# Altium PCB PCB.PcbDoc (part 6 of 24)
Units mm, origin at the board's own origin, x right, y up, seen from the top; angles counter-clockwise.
Board outline 100 x 160 mm, 10 copper layers (TOP_L1, L2, L3, L4, L5, L6, L7, L8, L9, BOTTOM_L10), stack 1.946 mm thick; 1358 components, 1149 nets, 6777 pads, 10914 vias.
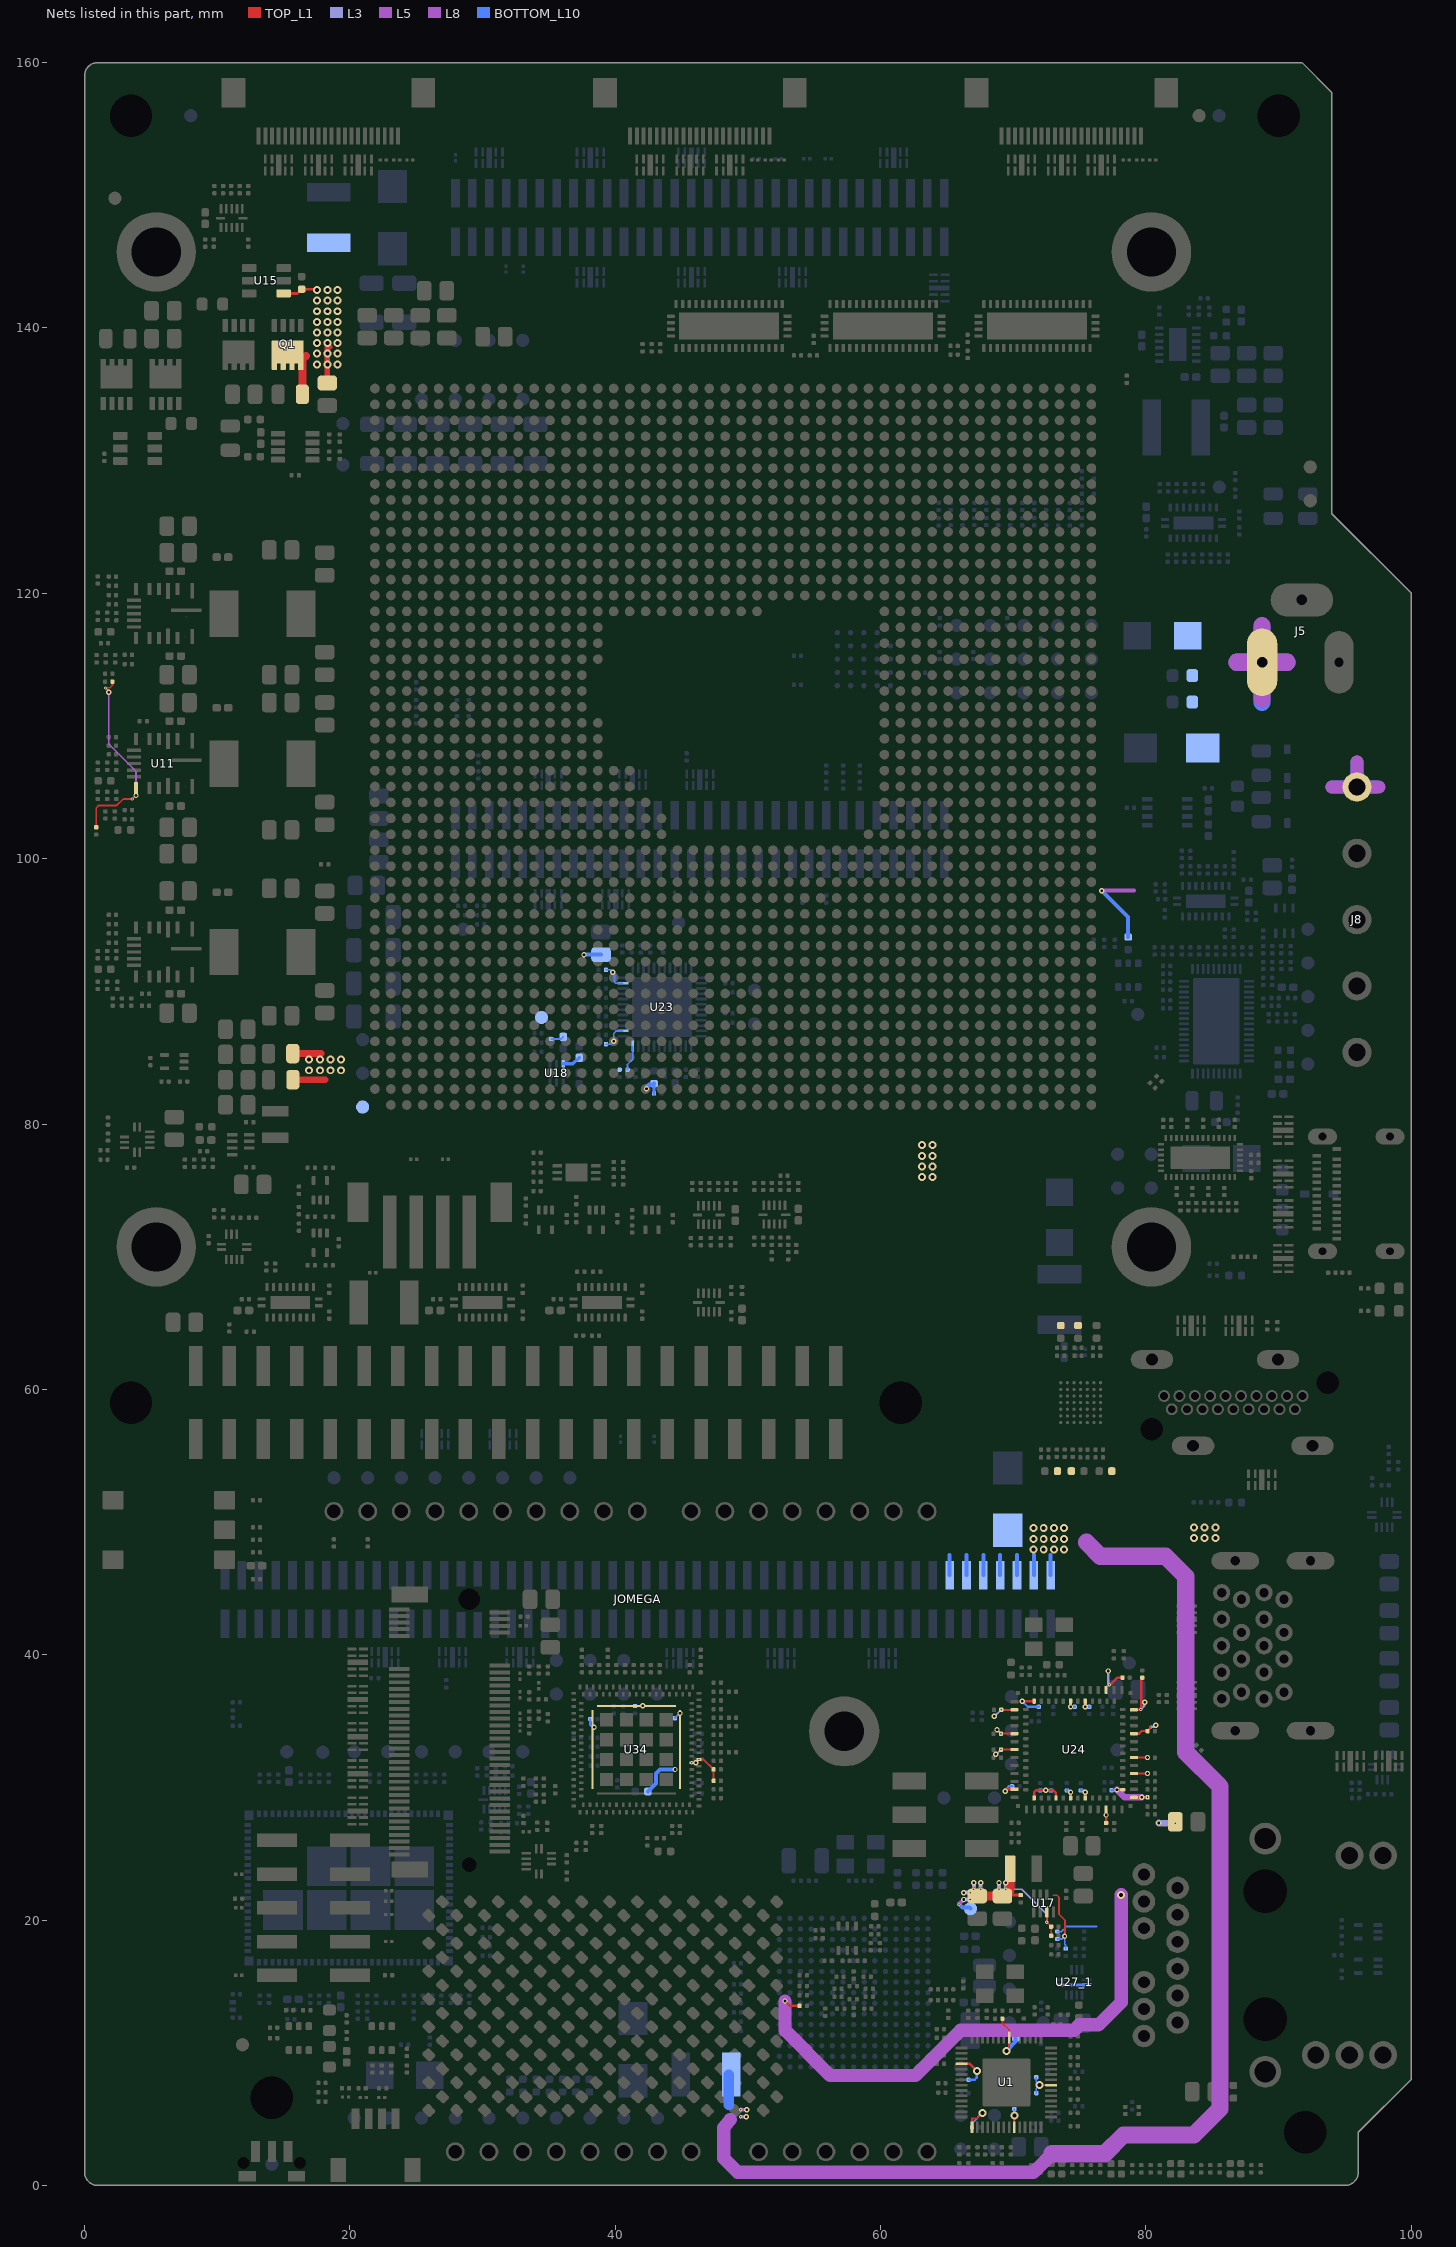
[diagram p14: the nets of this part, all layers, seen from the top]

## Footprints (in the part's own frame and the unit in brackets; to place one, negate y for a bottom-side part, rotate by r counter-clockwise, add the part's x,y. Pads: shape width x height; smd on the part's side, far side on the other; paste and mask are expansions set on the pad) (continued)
"WSON8 TI DDR 3x3mm 12 pins pitch 0.5mm" [mm]
  rrect25% 0.62x0.25 smd mask+0.05: 1(-1.39,1.25) 2(-1.39,0.75) 3(-1.39,0.25) 4(-1.39,-0.25) 5(-1.39,-0.75) 6(-1.39,-1.25) 7(1.39,-1.25) 8(1.39,-0.75) 9(1.39,-0.25) 10(1.39,0.25) 11(1.39,0.75) 12(1.39,1.25)
  rect 1.3x2.5 smd paste-2539.97 mask+0.05: 13(0,0)
  silkscreen extent -1.7,1.73 -1.6,1.83, body extent -1.51,-1.5 1.51,1.5, height 0.8

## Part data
C1 C2 C3 C4 C5 C6 C7 C8 C10 C11 C12 C13 C14 C16 C17 C18 C19 C20 C21 C22 C25 C26 C27 C28 C29 C30 C31 C32 C33 C34 C36 C43 C45 C46 C47 C49 C54 C55 C56 C57 C58 C59 C60 C61 C62 C67 C68 C69_1 C69_2 C69_3 C71 C94 C101 C111 C112 C113 C118 C119 C123 C124 C128 C129 C130 C131 C134 C146 C150 C152 C154 C156 C158 C163 C165 C166 C168 C170 C172_1 C172_2 C172_3 C172_4 C172_5 C173_1 C173_2 C173_3 C173_4 C173_5 C174_1 C174_2 C174_3 C174_4 C174_5 C175_1 C175_2 C175_3 C175_4 C175_5 C179_1 C179_2 C179_3 C179_4 C179_5 C179_6 C180 C181 C182 C183 C184 C185 C186 C188 C189 C190 C191 C192 C193 C194 C195 C196 C197 C198 C199 C202 C203 C204 C206 C207 C210 C211 C212 C213 C214 C215 C224 C225 C228 C229 C230 C231 C232 C233 C234 C235 C236 C237 C238 C239 C240 C241 C242 C243 C244 C245 C247 C251 C257 C258 C260 C262 C263 C265 C266 C267 C268 C269 C270 C271 C272 C273 C274 C275 C277 C278 C279 C281 C282 C283 C289 C291 C297 C300 C305 C306 C309 C310 C314 C324 C325 C328 C329 C330 C331 C338: library part C0113-A.6, "CAP CHIP 0201 100nF 10% 10V X5R", Case Code (Imperial)=0201, Dielectric=X5R, Manufacturer="Samsung Electro-Mechanics", Tolerance=10%, Voltage=10V
C9 C15 C42 C48 C63 C65 C85 C95 C106 C107 C108 C109 C110 C114 C136 C151 C153 C155 C157 C159 C160 C161 C162 C164 C167 C169 C205 C209 C217 C253 C254 C304 C308 C345 C346 C347 C348 C360: library part C0002-A.15, "CAP CHIP 0201 1uF 20% 6.3V X5R", Case Code (Imperial)=0201, Dielectric=X5R, Manufacturer=Murata, Tolerance=20%, Voltage=6.3V
C23 C24 C97 C105 C218 C219: library part C0003-A.15, "CAP CHIP 0201 12pF 5% 25V C0G", Case Code (Imperial)=0201, Dielectric=C0G, Manufacturer=Murata, Tolerance=5%, Voltage=25V
C35 C37 C38 C39 C81 C82 C83 C103 C104 C115 C120 C125 C147 C171 C177 C178 C187 C201 C221 C222 C223 C226 C227 C249 C250 C252 C255 C276 C311 C312 C313 C315 C316 C317 C318 C355 C359: library part C0199-A.1, "CAP CHIP 0805 47uF 20% 6.3V X5R", Case Code (Imperial)=0805, Dielectric=X5R, Manufacturer=KEMET, Tolerance=20%, Voltage=6.3V
C40 C41: library part C0197-A.2, "CAP CHIP 0402 390pF 10% 50V X7R", Case Code (Imperial)=0402, Dielectric=X7R, Manufacturer=Murata, Tolerance=10%, Voltage=50V
C44 C64 C70 C72 C132 C133 C137 C139 C176_1 C176_2 C176_3 C176_4 C176_5 C220_1 C220_2 C220_3 C220_4 C220_5 C259 C286 C287 C296 C332: library part C0037-A.14, "CAP CHIP 0402 4.7uF 20% 6V3 X5R", Case Code (Imperial)=0402, Dielectric=X5R, Manufacturer=Hottech, Manufacturer 2="Samsung Electro-Mechanics", Manufacturer 3="Murata Electronics", Part number 2=CL05A475KQ5NRNC, Part number 3=GRM155R60J475ME47D, Tolerance=20%, Voltage=6.3V
C50 C51 C52 C53: library part C0201-A.1, "CAP CHIP 0201 330nF 10% 25V X5R", Case Code (Imperial)=0201, Dielectric=X5R, Manufacturer="Samsung Electro-Mechanics", Tolerance=10%, Voltage=25V
C66: library part C0059-A.14, "CAP CHIP 0805 4.7nF 10% 1000V X7R", Case Code (Imperial)=0805, Dielectric=X7R, Manufacturer="PSA Shenzen", Manufacturer 2=KEMET, Part number 2=C0805V472KDRACTU, Part number 3=C0805C472KDRACTU, Tolerance=10%, Voltage=1kV
C73 C74 C76 C77 C78 C87 C88 C89 C98 C99 C117 C122 C135 C200 C208 C216 C288 C292 C294 C302 C352 C356 C357: library part C0158-A.3, "CAP CHIP 0805 10uF 20% 50V X5R", Case Code (Imperial)=0805, Dielectric=X5R, Manufacturer="Murata Electronics", Tolerance=20%, Voltage=50V
C75 C79 C84 C86 C90 C96 C100 C301 C303 C319 C320 C321 C333 C350 C351 C353 C354: library part C0015-A.14, "CAP CHIP 0402 100nF 10% 50V X5R", Case Code (Imperial)=0402, Dielectric=X5R, Manufacturer=Murata, Tolerance=10%, Voltage=50V
C80 C91 C102 C121 C126: library part C0114-A.6, "CAP CHIP 0201 33pF 5% 6.3V C0G", Case Code (Imperial)=0201, Dielectric=C0G, Manufacturer="Murata Electronics", Tolerance=5%, Voltage=6.3V
C92 C93 C140 C141 C142 C143 C148 C149 C334 C335 C336 C337: library part C0166-A.1, "CAP CHIP 1206 100uF 20% 10V X5R", Case Code (Imperial)=1206, Dielectric=X5R, Manufacturer=Murata, Tolerance=20%, Voltage=10V
C116 C127 C138: library part C0009-A.15, "CAP CHIP 0402 10nF 10% 50V X7R", Case Code (Imperial)=0402, Dielectric=X7R, Manufacturer=Hottech, Manufacturer 2="Murata Electronics", Manufacturer 3=YAGEO, Part number 2=CC0402KRX7R9BB103, Tolerance=10%, Voltage=50V
C144 C145: library part C0198-A.1, "CAP CHIP 0201 180pF 5% 50V C0G", Case Code (Imperial)=0201, Dielectric=C0G, Manufacturer=Murata, Tolerance=5%, Voltage=50V
C246_1 C246_2 C246_3 C246_4 C246_5 C246_6: library part C0112-A.6, "CAP CHIP 0201 10nF 10% 6.3V X7R", Case Code (Imperial)=0201, Dielectric=X7R, Manufacturer=Murata, Manufacturer 2=Yageo, Tolerance=10%, Voltage=6.3V
C248 C295: library part C0144-A.3, "CAP CHIP 0201 10pF 5% 50V C0G", Case Code (Imperial)=0201, Dielectric=C0G, Manufacturer=Yageo, Tolerance=5%, Voltage=50V
C256 C293: library part C0209-A.1, "CAP CHIP 0805 10nF 250V X7R", Case Code (Imperial)=0805, Dielectric=X7R, Manufacturer=Murata, Tolerance=10%, Voltage=250V
C261 C264: library part C0203-A.1, "CAP CHIP 0201 6pF 0.25pF 25V C0G", Case Code (Imperial)=0201, Dielectric=C0G, Manufacturer=Murata, Tolerance=0.25pF, Voltage=25V
C280 C284 C290 C298: library part C0113-A.6, "CAP CHIP 0201 100nF 10% 10V X5R", Case Code (Imperial)=0201, Dielectric=X5R, Manufacturer="Samsung Electro-Mechanics", Tolerance=10%
C285: library part C0202-A.1, "CAP CHIP 0201 220pF 10% 50V X7R", Case Code (Imperial)=0201, Dielectric=X7R, Manufacturer=Murata, Tolerance=10%, Voltage=50V
C299 C307 C322 C323 C326 C327: library part C0004-A.15, "CAP CHIP 0201 220nF 20% 6.3V X5R", Case Code (Imperial)=0201, Dielectric=X5R, Manufacturer=Murata, Tolerance=20%, Voltage=6.3V
C339 C343: library part C0063-A.3, "CAP CHIP 0603 1nF 10% 50V X7R", Case Code (Imperial)=0603, Dielectric=X7R, Manufacturer="Samsung Electro-Mechanics", Tolerance=10%, Voltage=50V
C340 C344: library part C0040-A.14, "CAP CHIP 0603 10nF 10% 50V X7R", Case Code (Imperial)=0603, Dielectric=X7R, Manufacturer=Walsin, Manufacturer 2=Hottech, Part number 2=C1608B103K500NT, Part number 3=CL10B103KC8NNNC, Tolerance=10%, Voltage=50V
C341: library part C0043-A.14, "CAP CHIP 0603 100nF 10% 50V X7R", Case Code (Imperial)=0603, Dielectric=X7R, Manufacturer=Walsin, Manufacturer 2=Hottech, Manufacturer 3="Samsung Electro-Mechanics", Part number 2=C1608B104K500NT, Part number 3=CL10B104KB8NNNC, Tolerance=10%, Voltage=50V
C342 C361: library part C0117-A.6, "CAP CHIP 0402 4.7pF ±0.5pF 50V C0G", Case Code (Imperial)=0402, Dielectric=C0G, Manufacturer=AVX, Tolerance=4.7%, Voltage=50V
C349: library part C0210-A.1, "CAP CHIP 0201 4pF 0.1pF 50V C0G", Case Code (Imperial)=0201, Dielectric=C0G, Manufacturer=Murata, Tolerance=0.1pF, Voltage=50V
C358: library part C0115-A.6, "CAP CHIP 0201 22pF 5% 25V C0G", Case Code (Imperial)=0201, Dielectric=C0G, Manufacturer=Yageo, Tolerance=5%, Voltage=25V
D1 D22 D23: library part D0098-A.2, "TVS BIDIRECTIONAL SMD Vr 24V, Vbr min 27.27V, 350W, SOD-323"
D2 D5 D37 D43: library part D0070-A.2, "TVS BIDIRECTIONAL SMD Vr 24V, Vbr min 26.7V, 600W, SMB", Manufacturer=Littlefuse, Manufacturer 2=Bourns, Manufacturer 3=Hottech
D3 D4 D9 D44: library part D0109-A.2, "DIODE SCHOTTKY SMD 3A 40V SMA DO214AC", Forward Current=3A, Forward Voltage=0.39V, Manufacturer=Panjit, Max Reverse Voltage (DC)=40V, Part Number=SX34-AU_R1_000A1
D6_1 D6_2 D6_3 D7_1 D7_2 D7_3 D8_1 D8_2 D8_3 D13 D14 D16 D18 D19 D20 D25 D26 D28 D29 D30 D31 D32 D36 D38 D39 D72 D73 D74 D75 D76 D77 D78 D79 D90 D91 D92 D93 D94 D95 D96 D97 D101 D102 D103 D104 D105: library part D0097-A.6, "TVS UNIDIRECTIONAL 4CH 0.8pF 5V SLP2510P8 10-pin 2.5x1.0x0.58mm", Manufacturer=SEMTECH
D10_1 D10_2 D10_3 D11_1 D11_2 D11_3 D12 D15_1 D15_2 D15_3 D17 D21 D24 D27 D33 D34 D35 D40 D41 D42 D61 D62 D63 D64 D65 D66 D67 D69 D70 D71 D80 D81 D82 D83 D84 D85 D86 D87 D88 D89 D98 D99 D100 D106: library part D0099-5, "TVS BIDIRECTIONAL SMD Vr 5.5V, Vbr min 5.8V, 0.62x0.32mm", Manufacturer=TOSHIBA, Power max=80W
DL1_1 DL1_2 DL1_3 DL1_4: library part L0014-A.13, "LED RGB DIFFUSED PICOLED SMD", Case Code (Imperial)=0404, Color=Blue,Green,Red, Forward Current=20mA, Forward Voltage=3V, Lens Color=White, Manufacturer=Liteon, Max Operating Temperature=85°C, Min Operating Temperature=-40°C, Test Current=5mA
DL2: library part L0024-A.4, "LED SMD 0603 RED 625nm, water clear, 42 to 88 mcd, 120 degrees, 1.6x0.8x0.6mm", Manufacturer="Shenzen Corehy Technology"
DL3: library part L0009-A.6, "LED SMD 0603 GREEN/568 15mcd 120^", Manufacturer=Liteon
F1 F4: library part P0002-A.7, "PTC RESET FUSE 15V 500MA 1812 LOGO OO ARDUINO", Case Code (Imperial)=1812, Case Code (Metric)=4532, Current Rating=100A, Hold Current=500mA, Manufacturer=Bourns, Max Operating Temperature=85°C, Min Operating Temperature=-40°C, Operating Supply Voltage=15V, Package Quantity=2000, Power Dissipation=800mW, Resistance=150mR, Trip Current=1A
F2: library part P0027-A.1, "PTC Ihold 1.1A Itrip 2.2A 33V 1812", Manufacturer="Bel Fuse"
F3: library part P0019-A.1, "PTC Ihold 1.5A Itrip 3A 24V 1812", Manufacturer=Bourns
Fiducial_1 Fiducial_2 Fiducial_3 Fiducial_4 Fiducial_5 Fiducial_6: library part UT0024-A.6
H1 H2 H3 H4: library part S0005-A.6, "M2.5 SPACER SMT ROUND STEEL H=5mm", Manufacturer="Würth Elektronik"
H5: library part S0074-A.2, "M2 SPACER SMT ROUND STEEL H=4mm", Manufacturer="Wurth Elektronik"
J1: library part J0010-A.12, "CONN RCPT USB3.1 TYPEC 24POS SMD", Manufacturer=Hirose
J2: library part J0561-A.4, "CONN ETH 1x1 RJ45 TH 10/100/1000/2500 integrated magnetics, LED GREEN/YELLOW/ORANGE, micro profile 17.8x24.2x11.55mm", Manufacturer=TRXCOM
J3_1 J3_2 J3_3: library part J0553-A.2, "CONN FFC/FPC Connector, 22 Contact(s), 1 Row(s), BOTTOM CONTACT, Female, Right Angle, 0.5mm Pitch", Manufacturer=Hirose
J4: library part J0578-A.2, "CONN HDMI RIGHT ANGLE FEMALE 19 POSITIONS 7.75x23.06x16.4mm signals pins lengths 2.3mm", Manufacturer="Contact technology"
J5: library part J0579-A.2, "CONN PWR JACK TH 2.1X5.5mm 1.6mm PCB", Manufacturer=POWERWAY
J6: library part J0572-A.1, "CONN HEADER MALE 40POS 2x20 2.54mm SMD 6mm pin length", Insulation Color=Black, Manufacturer=4UCONN
J7: library part J0560-A.4, "CONN TH USB-A x2 stacked USB3.0 tab blue", Manufacturer=ATTEND
J8: library part J0563-A.5, "CONN SCREW TERMINAL 5 POS pitch 5mm height 13.6mm BLACK", Manufacturer=Degson
J10: library part J0573-A.2, "CONN PCIE-based M.2 NGFF, KEY M, heigth 5.8mm board heigth 4.14mm gold plated, TOP MOUNT", Manufacturer=Amphenol
J13: library part J0005-A.3, "CONN JST SH 1mm 4POS HORIZONTAL TIN QWIIC", LCSC Part #=C160404, Manufacturer=JST
JANALOG: library part J0063-A.10, "JANALOG UNO header 2.54mm with 8+6 pins, custom 5.08mm pitch between them, custom silkscreen print on side", Manufacturer=4UCONN
JCTL: library part J0570-A.1, "CONN HEADER MALE 10POS 2x5 2.54mm SMD", Insulation Color=Black, Manufacturer=4UCONN
JDIGITAL: library part J0035-A.13, "JDIGITAL UNO header 2.54mm with 8+10 pins, custom 4.06mm pitch between them, custom silkscreen print on side", Manufacturer=4UCONN
JFAN: library part J0557-A.2, "CONN Header SMD 1x4 vertical polarized", Manufacturer=JST
JMEDIA JMISC: library part J0565-A.3, "CONN HEADER FEMALE VERTICAL SMD 1.27mm 2x30 POS heigth 4.4mm", Manufacturer=Greenconn
JOMEGA: library part J0574-A.2, "CONN HEADER FEMALE VERTICAL SMD 1.27mm 2x50 POS heigth 4.4mm", Manufacturer=Greenconn
JSPI: library part J0569-A.3, "CONN HEADER MALE 6POS 2x3 2.54mm SMD", Manufacturer=4UCONN
L1 L2 L6 L11 L12 L13 L14 L15 L16 L17 L18 L19 L20: library part I0028-A.10, "FERRITE SMD 0402 120Ohm 25% 100MHz Ferrite 2A", Case Code (Imperial)=0402, Case Code (Metric)=1005, Current=2A, DC Resistance (DCR)=55mR, Inductance=120µH, Manufacturer=Murata, Max Operating Temperature=125°C, Min Operating Temperature=-55°C, Package Quantity=10000, Test Frequency=100MHz, Tolerance=25%
L3 L4 L5: library part I0124-A.1, "IND 0.56uH 20%, max 5mR, IRMS 16.5A, Isat 25.5A, 7.3x6.6x3mm", Case Code (Metric)=7.3x6.6x3mm, Inductance=560nH, Manufacturer=K-WELL, Max Operating Temperature=125°C, Tolerance=20%
L7 L8: library part I0127-A.3, "IND SMD 1uH 20% ISAT 4.5A IRMS 3.4A 55mR MAX 2.5x2.1.2mm", Case Code (Metric)=2520, Inductance=1µH, Manufacturer=MPS, Max Operating Temperature=125°C, Resonant frequency=88MHz, Tolerance=20%
L9: library part I0132-A.2, "IND 0201 0.6nH 1A 30mR", Inductance=600pH
L10: library part I0133-A.2, "IND SMD 4.7uH 20%, DCR max 65mR, I sat 3A, I RMS 2.2A, package 5x5mm height 3mm", Inductance=4.7µH, Manufacturer="Shun Xiang Nuo", Tolerance=20%
L21: library part I0019-A.10, "INDUCTOR SMD 0806 2.2uH 1.2A", Case Code (Imperial)=0806, Case Code (Metric)=2016, Current=1.2A, DC Resistance (DCR)=138mR, Inductance=2.2µH, Manufacturer=Murata, Max Operating Temperature=125°C, Min Operating Temperature=-55°C, Package Quantity=1, Test Frequency=1MHz, Tolerance=30%
LED1 LED2 LED3 LED4 LED5 LED6 LED7 LED8 LED9 LED10 LED11 LED12 LED13 LED14 LED15 LED16 LED17 LED18 LED19 LED20 LED21 LED22 LED23 LED24 LED25 LED26 LED27 LED28 LED29 LED30 LED31 LED32 LED33 LED34 LED35 LED36 LED37 LED38 LED39 LED40 LED41 LED42 LED43 LED44 LED45 LED46 LED47 LED48 LED49 LED50 LED51 LED52 LED53 LED54 LED55 LED56 LED57 LED58 LED59 LED60 LED61 LED62 LED63 LED64 LED65 LED66 LED67 LED68 LED69 LED70 LED71 LED72 LED73 LED74 LED75 LED76 LED77 LED78 LED79 LED80 LED81 LED82 LED83 LED84 LED85 LED86 LED87 LED88 LED89 LED90 LED91 LED92 LED93 LED94 LED95 LED96 LED97 LED98 LED99 LED100 LED101 LED102 LED103 LED104: library part L0040-A.2, "LED SMD 0603 BLUE 468nm, water clear, 11-45 mcd, 138 deg", Manufacturer=Liteon
LOVE TP1 TP2 TP3 TP4 TP5 TP6 TP7 TP8 TP9 TP10 TP11 TP12 TP13 TP14 TP15 TP16 TP17 TP18 TP19 TP20 TP21 TP22 TP23 TP24 TP25 TP26 TP27 TP28 TP29 TP30 TP31 TP32 TP33 TP34 TP35 TP36 TP37 TP38 TP39 TP40 TP41 TP42 TP43 TP44 TP45 TP46 TP47 TP48 TP49 TP50 TP51 TP52 TP53 TP54 TP55 TP56 TP57 TP58 TP59 TP60 TP61 TP62 TP63 TP64 TP65 TP66 TP67 TP68 TP69 TP70 TP71 TP72 TP73 TP74 TP75 TP76 TP77 TP78 TP79 TP80 TP81 TP82 TP83 TP84 TP85 TP86 TP87 TP88 TP89 TP90 TP91 TP92 TP93 TP94 TP95 TP_FLASH_SAIL_1V8 TP_FLASH_SAIL_GND: library part UT0013-A.6, Manufacturer="This is not a component"
MODULE1: library part M0029-A.19, "MODULE BGA 1883 balls 57.5x57.5mm", Manufacturer=Qualcomm, Part Number="MODULE BGA"
PB1: library part B0005-A.11, "PUSHBUTTON SMD 6x6 5 PINS", Manufacturer=C&K
PB2: library part B0013-A.8, "PUSHBUTTON SMD VERTICAL ANCHORS 4x3.4mm", Manufacturer=E-Switch, Max Operating Temperature=85°C, Min Operating Temperature=-35°C
Q1 Q2 Q5 Q6: library part T0065-2, "MOSFET N-CH 60V 18A PowerPAK 1212-8W 3.3x3.3mm", Manufacturer=Vishay
Q3 Q4 Q7: library part T0011-A.12, "MOSFET 2N-CH 60V 0.32A SOT363", Manufacturer="Diodes Inc.", Manufacturer 2=Nexperia, Manufacturer Part Number 2=2N7002PS,115
R1 R2 R3 R4 R5 R12 R13 R14 R15 R31 R32 R33 R34 R35 R36 R37 R38 R39 R40 R41 R42 R43 R115 R128: library part R0235-A.13, "RES CHIP 0201 100R 1% 1/20W", Case Code (Imperial)=0201, Manufacturer=YAGEO, Power=50mW, Temperature coefficient=200ppm, Tolerance=1%
R6 R7 R136 R138 R210 R211 R286 R287 R295 R296 R297 R298 R303 R304 R338 R340: library part R0376-A.1, "RES CHIP 0201 5k1 1% 1/20W", Case Code (Imperial)=0201, Manufacturer=Panasonic, Power=50mW, Temperature coefficient=200ppm, Tolerance=1%
R8 R9 R10 R11 R105 R106 R110 R111 R207_1 R207_2 R207_3 R207_4 R208_1 R208_2 R208_3 R208_4 R209 R288 R289 R290 R293 R294 R299 R300 R301 R302 R305 R306 R307 R308 R309: library part R0149-A.21, "RES CHIP 0201 330R 1% 1/20W", Case Code (Imperial)=0201, Manufacturer=Yageo, Manufacturer 2="Samsung Electro-Mechanics", Power=50mW, Temperature coefficient=200ppm, Tolerance=1%
R16 R17 R18 R19 R20 R24 R27 R28 R29 R30 R44 R45 R46 R47 R48 R49 R50 R51 R52 R53 R54 R55 R56 R112 R116 R121 R122 R127 R135 R150 R154 R155 R158 R159 R160 R164 R168_1 R168_2 R168_3 R168_4 R168_5 R169 R170 R171 R172 R173 R175 R176 R177 R179 R182 R184 R191 R217 R238 R239 R240 R241 R242 R243 R261 R263 R265 R269 R315 R317 R323 R324 R325 R326_1 R326_2 R326_3 R326_4 R326_5 R327 R328 R329 R356 R375 R376 R395 R396 R428 R429 R431 R432 R455 R456 R461 R463 R464 R467 R468 R487 R489: library part R0145-A.21, "RES CHIP 0201 10k 1% 1/20W", Case Code (Imperial)=0201, Manufacturer=Yageo, Manufacturer 2="Samsung Electro-Mechanics", Power=50mW, Temperature coefficient=200ppm, Tolerance=1%
R21 R22: library part R0323-A.1, "RES CHIP 0805 0R 1% 1/8W", Case Code (Imperial)=0805, Manufacturer=YAGEO, Power=125mW, Temperature coefficient=0ppm, Tolerance=1%
R23 R57 R58 R59 R60 R61 R62 R63 R64 R65 R66 R67 R68 R77 R78 R79 R80 R81 R82 R83 R84 R90 R93 R96 R193 R215 R233 R249 R258 R266 R267 R333 R334 R335 R371 R372 R373 R374 R406 R407 R413 R414 R415 R416 R465 R466 R478: library part R0151-A.21, "RES CHIP 0201 4k7 1% 1/20W", Case Code (Imperial)=0201, Manufacturer=Yageo, Power=50mW, Temperature coefficient=200ppm, Tolerance=1%
R25 R26 R107 R119 R123 R132 R134 R139 R141 R142 R144 R148 R234 R236 R248 R271 R339 R341 R357 R397 R472 R473 R474: library part R0398-A.1, "RES CHIP 0201 24k 1% 1/20W", Case Code (Imperial)=0201, Manufacturer=YAGEO, Power=50mW, Temperature coefficient=200ppm, Tolerance=1%
R69 R70 R71 R72 R73 R74 R75 R76: library part R0152-A.22, "RES CHIP 0201 49R9 1% 1/20W", Case Code (Imperial)=0201, Manufacturer=Yageo, Power=50mW, Temperature coefficient=200ppm, Tolerance=1%
R85 R222 R223 R246 R247 R402 R436 R437 R449 R450: library part R0199-A.20, "RES CHIP 0201 220k 1% 1/20W", Case Code (Imperial)=0201, Manufacturer=Yageo, Power=50mW, Temperature coefficient=200ppm, Tolerance=1%
R86 R87 R94 R95 R97 R98 R99 R100 R101 R102 R103 R104 R113 R114 R125 R126 R133 R137 R140 R143 R151 R152 R153 R161 R163 R174 R178 R186 R187 R188 R189 R192 R216 R218 R219 R221 R224 R225 R226 R227 R228 R232 R235 R237 R259 R260 R262 R264 R274 R275 R277 R278 R279 R280 R281 R282 R283 R284 R285 R291 R292 R310 R311 R312 R313 R314 R316 R318 R336 R337 R343 R344 R345 R346 R347 R348 R349 R350 R351 R353 R354 R355 R358 R359 R360 R361 R362 R363 R364 R365 R366 R367 R368 R369 R370 R377 R378 R379 R380 R381 R382 R383 R384 R385 R388 R399 R400 R401 R403 R404 R405 R408 R409 R410 R411 R417 R418 R419 R421 R427 R430 R433 R434 R435 R438 R439 R440 R441 R442 R443 R444 R445 R446 R447 R448 R451 R452 R453 R454 R462 R469 R470 R471 R475 R476 R477 R479 R480 R481 R482 R484 R485 R486 R488 R492 R493 R494 R495 R496 R497 R499 R501 R504 R508 R509 R510: library part R0140-A.21, "RES CHIP 0201 0R", Case Code (Imperial)=0201, Manufacturer=Vishay, Power=50mW, Temperature coefficient=0ppm, Tolerance=0%
R88 R89 R109 R194: library part R0394-A.1, "RES CHIP 0402 2M 1% 1/16W", Case Code (Imperial)=0402, Manufacturer=YAGEO, Power=62.5mW, Temperature coefficient=100ppm, Tolerance=1%
R91 R92 R124 R149 R162 R165 R166 R167 R205_1 R205_2 R205_3 R205_4 R206_1 R206_2 R206_3 R206_4 R250 R251 R252 R253 R254 R255 R256 R257 R268 R270 R319 R320 R321 R322 R330 R331 R332 R386 R387 R392 R393 R394 R412 R422 R423 R424 R425 R458 R503: library part R0195-A.22, "RES CHIP 0201 1k 1% 1/20W", Case Code (Imperial)=0201, Manufacturer=Yageo, Power=50mW, Temperature coefficient=200ppm, Tolerance=1%
R108 R195 R196 R197 R198 R199 R200 R201 R202 R203 R204 R272 R273: library part R0170-A.23, "RES CHIP 0402 10R 1% 1/16W", Case Code (Imperial)=0402, Manufacturer=YAGEO, Power=62.5mW, Temperature coefficient=200ppm, Tolerance=1%
R117 R118 R129 R146 R147 R230 R245 R398 R420 R460: library part R0001-A.24, "RES CHIP 0402 100k 1% 1/16W", Case Code (Imperial)=0402, Manufacturer=Vishay, Power=62.5mW, Temperature coefficient=100ppm, Tolerance=1%
R120 R426: library part R0396-A.1, "RES CHIP 0201 22k1 1% 1/20W", Case Code (Imperial)=0201, Manufacturer=YAGEO, Power=50mW, Temperature coefficient=200ppm, Tolerance=1%
R130 R156 R157 R180 R181 R220 R244 R352 R389 R390 R391 R498: library part R0146-A.21, "RES CHIP 0201 100k 1% 1/20W", Case Code (Imperial)=0201, Manufacturer=Yageo, Manufacturer 2="Samsung Electro-Mechanics", Power=50mW, Temperature coefficient=200ppm, Tolerance=1%
R131: library part R0395-A.1, "RES CHIP 0201 13k7 1% 1/20W", Case Code (Imperial)=0201, Manufacturer=YAGEO, Power=50mW, Temperature coefficient=200ppm, Tolerance=1%
R145 R183 R342: library part R0399-A.1, "RES CHIP 0201 18k 1% 1/20W", Case Code (Imperial)=0201, Manufacturer=YAGEO, Power=50mW, Temperature coefficient=200ppm, Tolerance=1%
R185: library part R0400-A.1, "RES CHIP 0201 1k43 1% 1/20W", Case Code (Imperial)=0201, Manufacturer=YAGEO, Power=50mW, Temperature coefficient=200ppm, Tolerance=1%
R190: library part R0397-A.2, "RES CHIP 0201 9k09 1% 1/20W", Case Code (Imperial)=0201, Manufacturer=YAGEO, Power=50mW, Temperature coefficient=200ppm, Tolerance=1%
R212 R213: library part R0130-A.14, "RES CHIP 0805 100R 1% 1/8W 100ppm", Case Code (Imperial)=0805, Manufacturer=YAGEO, Power=125mW, Temperature coefficient=100ppm, Tolerance=1%
R214 R231: library part R0188-A.20, "RES CHIP 0603 10R 1% 1/10W", Case Code (Imperial)=0603, Manufacturer=Vishay, Power=100mW, Temperature coefficient=100ppm, Tolerance=1%
R229: library part R0132-A.12, "RES CHIP 0805 2mR 1% 1/2W", Case Code (Imperial)=0805, Manufacturer="ROHM Semiconductor", Power=500mW, Temperature coefficient=150ppm, Tolerance=1%
R276 R502 R505: library part R0131-A.13, "RES CHIP 0805 0R", Case Code (Imperial)=0805, Manufacturer=Vishay, Power=125mW, Temperature coefficient=0ppm, Tolerance=0%
R457 R459: library part R0105-A.22, "RES CHIP 0603 100R 1% 1/10W", Case Code (Imperial)=0603, Manufacturer=Vishay, Power=100mW, Temperature coefficient=100ppm, Tolerance=1%
R483 R511: library part R0423-A.1, "RES CHIP 0201 5.6M 1% 1/20W 200ppm", Case Code (Imperial)=0201, Manufacturer=YAGEO, Power=50mW, Temperature coefficient=200ppm, Tolerance=1%
R490 R491: library part R0286-A.3, "RES CHIP 0402 2k2 1% 1/16W", Case Code (Imperial)=0402, Manufacturer=Yageo, Manufacturer 2=Hottech, Part number 2=RI0402L2201FT, Power=62.5mW, Temperature coefficient=100ppm, Tolerance=1%
R500: library part R0420-A.1, "RES CHIP 0201 31k6 1% 1/20W 100ppm", Case Code (Imperial)=0201, Manufacturer=Vishay, Power=50mW, Temperature coefficient=100ppm, Tolerance=1%
R506 R507: library part R0422-A.1, "RES CHIP 0805 60R4 1% 1/8W 50ppm", Case Code (Imperial)=0805, Manufacturer=YAGEO, Power=125mW, Temperature coefficient=50ppm, Tolerance=1%
U1: library part U0492-A.6, "IC ETH PHY 2.5Gb, 7x7mm MQFN56", Manufacturer=Qualcomm
U2: library part U0506-A.2, "IC NOR FLASH, VDD 1.8V, OSPI, 256Mb x1/x8, BGA24 6x8mm", Manufacturer=Macronix
U3: library part U0520-A.5, "IC Cortex M33 250MHz, 4MB flash, 1.5MB RAM, TFBGA225 13x13mm", Manufacturer=ST
U4: library part U0524-A.1, "IC monostable multivibrator programmable pulse 1us to 33.6 DFN6 2x3mm", Manufacturer="Analog Devices"
U5: library part U0495-A.3, "IC Controller power delivery USB-C, QFN52 5x8mm", Manufacturer=Infineon
U6: library part U0499-A.3, "IC MUX Alt Mode Crossbar USB-C 10Gbps, QFN40 3x6mm", Manufacturer="Texas Instruments"
U7: library part U0505-A.4, "IC CAN FD PHY 5Mbps, VIO pin, Standby, VDFN8 3x3mm", Manufacturer=Microchip
U8 U9 U19 U25 U31 U32 U35 U36: library part U0494-A.2, "IC buffer open drain, 1.65V to 5.5V, 32mA sink current, SOT-5X3 1.6mmx1.6mm", Manufacturer="Texas Instruments"
U10_1 U10_2 U10_3: library part U0522-A.2, "IC MUX SWITCH 6GHz, 12 channel 2:1 bidirectional switch, port A 6.9GHz port B 7.5GHz, Vcc 2.6V to 4.5V, WQFN42 9x3.5mm", Manufacturer="Texas Instruments"
U11 U13 U14: library part U0503-A.7, "IC Buck Vin 36V, Vout ADJ, Iout max 11A, with FSS, multi phase, QFN23 4x5mm", Manufacturer=MPS
U12: library part M0030-A.15, "Module 802.11a/b/g/n/ac/ax 2x2 MAC + BT 5.2, QCA2066, with 2 antenna pads, PCIe, LGA76 14x17.68mm", Manufacturer=USI
U15 U29: library part U0502-A.3, "IC Ideal diode and load switch controller with reverse input protection, 4.2V to 60V, EN pin 1.32V, SOT23-6", Manufacturer="Kinetic Technology"
U16 U17: library part U0504-A.5, "IC Buck Vin 5.5V, Vout ADJ, Iout max 3A, fsw 2.4MHz, QFN8 2x1.5mm", Manufacturer=MPS
U18: library part U0496-A.5, "IC LDO, Vin 1.6V - 5.5V, Vout ADJ, Iout 0.5A, SOT563 1.6x1.6mm", Manufacturer=MPS
U20: library part U0519-A.2, "IC MONITOR PWR/CURR/VOLT 16bit ADC I2C SOT23-THIN8 1.6x2.9x1.1 mm", Manufacturer="Texas Instruments"
U21_1 U21_2 U21_3 U21_4 U21_5: library part U0523-A.1, "IC TRANSLATOR LEVEL SHIFTER BIDIR 4b, push pull 110Mbps, open drain 1.2Mbps, VCCA 1.4V-3.6V, VCCB 1.6V-5.5V, VCCA≤VCCB, Output Enable, UQFN-12 2x1.7mm", Manufacturer="Texas Instruments"
U22: library part U0508-A.3, "IC DSI to HDMI converter, WLCSP49 3.5x3.5mm", Manufacturer="Analog Devices"
U23: library part U0313-A.5, "CODEC Audio CODEC, 4 IN microphone, stereo speaker out 3.2W, stereo headphone out, line output, I2C+I2S, QFN48 6x6", Manufacturer="Analog Devices"
U24: library part U0510-A.10, "IC PCIe x1 Gen2 to x4 USB 3.0 converter, QFN-MR100 9x9mm", Manufacturer="Texas Instruments"
U26: library part U0467-A.1, "IC BUCK Vin 4-36V, Iout 4A, max duty 97%, fsw 1.1MHz, WSON8 3x3mm", Manufacturer="Texas Instruments"
U27_1 U27_2 U27_3 U27_4 U27_5 U27_6: library part U0512-A.2, "IC Load Switch Vload 0.5V to 5.5V, 10mR at 5V, max 7A, programmable overcurrent limit, linear ramp control, logic ON 1.7V, VCC 3V to 5.5V, -40 to 125°C, QFN12 2x2mm", Manufacturer=MPS
U28: library part U0174-A.3, "IC SPDT,max 25R at VCC 4.5V tPD 1.2ns VCC 1.65V to 5V Iq max 10uA SOT363", Manufacturer="SG Micro", Manufacturer 2="ON Semiconductor", Part number 2=NLASB3157DFT2G
U30: library part U0518-A.2, "IC LDO, Vin 2.5V-40V, Vout ADJ, Iout 0.15A, Iq typ 15uA, QFN6 2x2mm", Manufacturer=MPS
U33_1 U33_2 U33_3 U33_4 U33_5: library part U0456-A.4, "IC TRANSLATOR LEVEL SHIFTER BIDIR 8b, push pull 110Mbps, open drain 1.2Mbps, VCCA 1.4V-3.6V, VCCB 1.6V-5.5V, VCCA≤VCCB, Output Enable, VQFN-20", LCSC Part #=C43138309, Manufacturer="Texas Instruments"
U34: library part U0511-A.14, "IC 3PCIe 2.0 Packet Switch 3-Port, 4-Lane aQFN136 10x10mm", Manufacturer="Diodes Incorporated"
Y1: library part X0031-A.3, "CRYSTAL 50MHz tolerance 10ppm stability 20ppm load 10pF 3.2x2.5mm", Frequency=50MHz, Frequency Stability=20ppm, Frequency Tolerance=10ppm, Load Capacitance=10pF, Manufacturer=Kyocera, Max Operating Temperature=105°C, Min Operating Temperature=-40°C, Series Resistance=22R
Y2: library part X0032-A.3, "CRYSTAL 48MHz tolerance 10ppm stability 20ppm load 10pF 3.2x2.5mm", ESR (Equivalent Series Resistance)=30, Frequency=48MHz, Frequency Stability=20ppm, Frequency Tolerance=10ppm, Load Capacitance=10pF, Manufacturer=Kyocera, Max Operating Temperature=85°C, Min Operating Temperature=-40°C, Series Resistance=30R
Y3: library part X0035-A.2, "CRYSTAL 48MHz tolerance 10ppm stability 15ppm load 10pF, shunt 2pF, ESR 30R, 3.2x2.5mm", ESR (Equivalent Series Resistance)=30, Frequency=48MHz, Frequency Stability=15ppm, Frequency Tolerance=10ppm, Load Capacitance=8pF, Manufacturer=ECS, Series Resistance=30R
Y4: library part X0003-A.5, "CRYSTAL 32.768kHz 20ppm 12.5pF SMD 1.6x0.9mm", Frequency=32.768kHz, Frequency Stability=0.12%, Frequency Tolerance=20ppm, Load Capacitance=12.5pF, Manufacturer="Citizen FineDevice", Max Operating Temperature=85°C, Min Operating Temperature=-40°C, Series Resistance=70kR

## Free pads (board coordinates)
  round 3 hole 3.2 unplated paste-2539.97 mask+1.3: MH(3.5,59) MH(3.5,156) MH(14.117,6.6) MH(61.5,59) MH(90,156) MH(92,4)

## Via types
v1: diameter 0.25, hole 0.1, TOP_L1 to L2, tented both sides, 3439 vias
v2: diameter 0.25, hole 0.1, L2 to L3, tented both sides, 2256 vias
v3: diameter 0.25, hole 0.1, L9 to BOTTOM_L10, tented both sides, 1685 vias
v4: diameter 0.25, hole 0.1, L8 to L9, tented both sides, 1675 vias
v5: diameter 0.4, hole 0.2, L3 to L8, tented both sides, 1251 vias
v6: diameter 0.6, hole 0.3, TOP_L1 to BOTTOM_L10, tented both sides, 600 vias
v7: diameter 0.24, hole 0.1, TOP_L1 to L2, tented both sides, 8 vias

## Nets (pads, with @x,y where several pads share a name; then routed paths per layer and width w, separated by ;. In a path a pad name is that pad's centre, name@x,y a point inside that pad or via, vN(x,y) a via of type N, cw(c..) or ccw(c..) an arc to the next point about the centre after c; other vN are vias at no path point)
"1V05_PG (PULLUP 1V8)_1": R85.1 R265.2 U17.1 | length 5.2
  TOP_L1 w0.127: U17.1@73.031,21.859 73.291,21.859 73.44,21.71 73.44,20.44 73.889,19.991 v1@73.889,18.783 ; v1(73.888,18.782) v1@73.889,18.783
  BOTTOM_L10 w0.127: R265.2@73.321,18.577 73.673,18.577 v3@73.866,18.77 ; v3(73.863,18.773) v3@73.866,18.77 ; R85.1@73.956,17.843 73.956,18.105 73.878,18.183 73.878,18.782 v3@73.866,18.77
  other v2: 73.888,18.782
  other v4: 73.863,18.773
  other v5: 73.863,18.773
"3V3_PG (PULLUP 3V3)_1": R124.2 R349.1 U11.1 U11.2 | length 15.7
  TOP_L1 w0.127: R349.1@0.875,102.366 0.875,103.821 1.066,104.012 2.431,104.012 2.912,104.493 v1(3.603,104.493) v5(3.875,104.765) U11.1@3.875,105.315 ; v1(1.581,112.862) 1.605,112.886 1.916,112.886 2.1,113.07 R124.2@2.1,113.34
  L3 w0.127: v1(1.581,112.862) 1.586,112.862 1.825,112.623 v5(1.825,112.535) ; v1(3.603,104.493) v5(3.875,104.765)
  L8 w0.127: v5(1.825,112.535) 1.825,108.64 3.875,106.59 v5(3.875,104.765)
  other v2: 3.603,104.493 1.581,112.862
7V-24V: C292.2 C339.1 C340.1 D5.2 D9.A D37.2 F2.1 F3.1 J5.1 J8.1 JOMEGA.1 JOMEGA.3 JOMEGA.5 JOMEGA.7 JOMEGA.9 JOMEGA.11 JOMEGA.13 Q1.D R212.2 R230.1 R245.1 U15.1 | length 151.8
  TOP_L1 w0.127: U15.1@14.989,142.597 U15.1@15,142.608
  TOP_L1 w0.2: U15.1@15,142.608 15.011,142.597 16.036,142.597 R245.1@16.357,142.918 v6@17.56,142.918
  TOP_L1 w0.4: Q1.D@15.3,138.2 Q1.D@16.075,138.2 ; C292.2@18.3,136.1 18.3,138.558 18.5,138.558
  TOP_L1 w0.6: R212.2@16.415,135 Q1.D@16.415,137.715 ; 16.515,137.715 16.7,137.9
  L5 w0.3: v3(76.657,97.588) 79.097,97.588
  L5 w1: 48.663,4.972 48.175,4.342 48.175,2.047 49.222,1 71.525,1 72.917,2.392 ; 94.012,105.4 J8.1@95.9,105.4 95.9,107.288 ; J8.1@95.904,105.396 97.569,105.396
  L5 w1.3: 72.917,2.392 76.892,2.392 78.306,3.806 83.606,3.806 85.575,5.775 85.575,30.075 82.996,32.654 82.996,45.9 81.473,47.423 76.561,47.423 75.514,48.47 ; 86.86,114.8 J5.1@88.748,114.8 ; 88.748,112.036 J5.1@88.748,114.8 ; 88.748,117.564 J5.1@88.748,114.8 ; 90.636,114.8 J5.1@88.748,114.8
  L8 w0.3: v3(49.458,5.175) v5(49.875,5.175) ; v3(49.458,5.709) 49.464,5.703 v5(49.915,5.703)
  BOTTOM_L10 w0.3: JOMEGA.13@65.196,46 65.196,47.533 ; JOMEGA.11@66.466,46 66.466,47.533 ; JOMEGA.9@67.736,46 67.736,47.533 ; JOMEGA.7@69.006,46 69.006,47.533 ; JOMEGA.5@70.276,46 70.276,47.533 ; JOMEGA.3@71.546,46 71.546,47.533 ; JOMEGA.1@72.816,46 72.816,47.533 ; v3(76.657,97.588) 78.657,95.588 R230.1@78.657,94.091
  BOTTOM_L10 w0.8: 48.539,6.073 F2.1@48.539,8.353
  BOTTOM_L10 w1: 94.012,105.4 J8.1@95.9,105.4 ; 95.9,107.288 J8.1@95.9,105.4 ; 97.364,105.4 J8.1@95.9,105.4
  BOTTOM_L10 w1.3: 86.86,114.8 J5.1@88.748,114.8 ; 88.748,111.782 J5.1@88.748,114.8 ; 88.748,117.378 J5.1@88.748,114.8 ; 90.636,114.8 J5.1@88.748,114.8
  other v4: 49.458,5.175 49.458,5.709 76.657,97.588
  other v5: 76.657,97.588
  other v6: 71.522,47.936 72.292,47.936 73.062,47.936 73.832,47.936 71.522,48.736 72.292,48.736 73.062,48.736 73.832,48.736 71.522,49.536 72.292,49.536 73.062,49.536 73.832,49.536 17.53,137.258 18.3,137.258 19.07,137.258 17.53,138.058 18.3,138.058 19.07,138.058 17.53,138.858 18.3,138.858 19.07,138.858 17.53,139.658 18.3,139.658 19.07,139.658 17.53,140.458 18.3,140.458 19.07,140.458 17.53,141.258 18.3,141.258 19.07,141.258 17.53,142.058 18.3,142.058 19.07,142.058 17.53,142.858 18.3,142.858 19.07,142.858
+1.28V: C136.2 C138.1 C139.1 C146.2 R134.1 TP85.X U18.3 U23.36 | length 4.3
  BOTTOM_L10 w0.127: R134.1@35.175,86.406 35.915,86.406 C138.1@36.075,86.566 ; C146.2@40.923,84.091 40.923,84.483 41.323,84.883 U23.36@41.323,85.866
  BOTTOM_L10 w0.25: U18.3@36.075,84.531 36.81,84.531 C139.1@37.275,84.996
+1V1: C14.2 C15.2 C31.2 C32.2 C33.2 C34.2 C124.2 C125.2 C126.2 C180.2 C181.2 C182.2 C183.2 C184.2 C185.2 C186.2 C188.2 C189.2 C190.2 C191.2 C192.2 C193.2 C194.2 C195.2 C196.2 C197.2 C198.2 C199.2 C200.2 C240.2 C241.2 C242.2 C243.2 C244.2 C311.2 L2.2 L8.2 L20.1 R144.2 TP86.X U1.7 U1.21 U1.32 U1.43 U1.51 U17.7 U24.A1 U24.A4 U24.A6 U24.A9 U24.A12 U24.A16 U24.A28 U24.A31 U24.A33 U24.A38 U24.A50 U24.B1 U24.B17 U24.B19 U24.B24 U24.B37 U24.B40 U24.B42 U24.B44 U34.B U34.L U34.P2 U34.R U34.R1 | length 72.5
  TOP_L1 w0.127: C33.2@69.175,12.57 69.175,12.225 69.681,11.719 U1.21@69.681,11.134 69.681,10.337 v6(69.481,10.137) ; U1.51@70.081,4.384 v6(70.081,5.259) ; v6(71.981,7.559) U1.7@72.856,7.559 ; U17.7@72.531,20.609 v2(72.531,19.834) C126.2@72.856,19.509 R144.2@72.856,18.809
  TOP_L1 w0.15: U34.R@38.291,32.849 38.291,34.542 v3(38.402,34.542) ; v2(46.311,32.099) 46.661,32.099 C244.2@47.411,31.349 C241.2@47.411,30.499 ; U1.43@66.881,4.384 66.881,5.059 67.269,5.059 v6(67.673,5.463) ; C199.2@69.066,32.849 C199.2@69.066,32.849 ; v2(69.066,34.049) U24.A31@70.091,34.049 ; v2(69.07,32.85) C199.2@69.066,32.849 ; v2(69.091,35.849) U24.A28@70.091,35.849 U24.A28@70.116,35.849 ; U24.A33@70.091,32.849 C199.2@69.066,32.849 ; U24.A1@79.091,29.249 v2(80.116,29.249) ; U24.A4@79.091,31.049 v2(80.09,31.049) ; U24.A6@79.091,32.249 v2(80.116,32.249)
  TOP_L1 w0.18: U1.32@66.106,9.159 66.724,9.159 v6(67.252,8.631) ; v2(69.383,29.717) 69.402,29.717 69.533,29.849 U24.A38@70.091,29.849 ; U24.B37@71.566,29.199 71.566,29.633 71.708,29.774 v4(72.441,29.774) 73.016,29.774 73.216,29.574 U24.B40@73.216,29.199 ; C180.2@76.991,27.324 v1(76.991,27.924) U24.A50@76.991,28.349 ; U24.A9@79.091,34.049 79.484,34.049 79.684,34.249 C185.2@80.116,34.249 ; U24.A12@79.091,35.849 79.549,35.849 79.575,35.874 v1(79.594,35.874) 79.594,35.893 79.609,35.908 79.609,36.015 79.628,36.034 79.628,38.019 79.644,38.035 79.644,38.202 79.709,38.267 C186.2@79.724,38.267 ; v2(80.09,31.049) v5(80.116,31.049) ; C185.2@80.116,34.264 80.357,34.504 80.357,34.535 v1(80.37,34.548)
  TOP_L1 w0.2: C311.2@69.181,21.809 69.256,21.884 C124.2@70.556,21.884 ; v1(70.664,36.493) 70.667,36.496 71.564,36.496 U24.B24@71.566,36.499 ; U24.B42@74.316,29.199 v1(74.316,29.624) ; v3(74.316,36.074) U24.B19@74.316,36.499 ; U24.B44@75.416,29.199 v1(75.416,29.624) ; v3(75.416,36.074) U24.B17@75.416,36.499 ; U24.A16@76.991,37.349 77.016,37.374 77.016,37.549 77.205,37.738 77.227,37.738 v2(77.236,37.747) 77.246,37.757 77.328,37.757 77.846,38.275 C193.2@78.225,38.275 ; v1(77.816,29.824) U24.B1@78.241,29.824
  TOP_L1 w0.3: v2(66.759,21.549) 66.761,21.55 67.022,21.55 C125.2@67.281,21.809 ; v1(66.759,22.069) 66.761,22.068 67.022,22.068 67.022,22.329 v1(67.021,22.331) ; C125.2@67.54,22.068 67.54,22.329 v2(67.541,22.331)
  TOP_L1 w0.7: C125.2@67.281,21.809 C311.2@69.181,21.809 ; C311.2@69.756,22.252 L8.2@69.756,23.859
  L5 w0.5: v1(77.816,29.824) 78.395,29.246 v5(79.688,29.246)
  L3 w0.127: v2(69.441,22.331) 70.631,22.331 72.531,20.431 v2(72.531,19.834)
  L3 w0.15: v1(45.761,31.849) v5(46.061,31.849) v2(46.311,32.099) ; v5(68.57,35.35) 68.581,35.35 69.08,35.849 v2(69.091,35.849) ; v5(68.673,32.505) 68.699,32.505 69.044,32.85 v2(69.07,32.85) ; v5(68.77,34.35) 68.77,34.348 69.066,34.051 v2(69.066,34.049) ; v5(79.688,29.246) 79.69,29.247 80.115,29.247 v2(80.116,29.249)
  L3 w0.18: v1(79.594,35.874) 79.858,36.139 79.858,36.383 v5(79.9,36.425) ; v2(80.09,31.049) v5(80.116,31.049) ; v1(80.37,34.548) 80.383,34.562 80.555,34.562 80.667,34.674 v5(80.727,34.674)
  L3 w0.2: v5(77.157,38.769) 77.157,37.84 77.236,37.761 v2(77.236,37.747)
  L3 w0.3: v5(66.27,21.55) v5(66.27,21.55) v2(66.759,21.549) ; v5(66.27,22.068) 66.271,22.069 v1(66.759,22.069) ; v1(67.021,22.331) 67.021,22.819 v5(67.022,22.82) ; v5(67.54,22.82) v5(67.54,22.82) v2(67.541,22.331) ; v1(68.921,22.331) 68.921,22.819 v5(68.922,22.82) ; v5(69.44,22.82) v5(69.44,22.82) v2(69.441,22.331)
  L3 w0.5: v5(80.963,27.315) 80.969,27.309 v2(82.211,27.309)
  L8 w0.3: v3(65.9,21.2) 65.92,21.2 v5(66.27,21.55)
  BOTTOM_L10 w0.127: v6(70.081,5.259) C32.2@70.081,5.759 ; C15.2@71.731,6.959 71.731,7.309 v6(71.981,7.559) 71.731,7.809 C14.2@71.731,8.159
  BOTTOM_L10 w0.15: C242.2@38.111,35.149 38.111,34.69 38.284,34.518 38.378,34.518 v3(38.402,34.542) ; C243.2@41.486,36.124 42.079,36.124 v1(42.079,36.144) ; C240.2@44.492,35.218 44.492,35.23 44.572,35.309 44.584,35.309 44.756,35.482 44.762,35.482 44.861,35.581 v3(44.879,35.581) ; C31.2@66.881,4.384 66.942,4.445 66.942,4.732 v6(67.673,5.463)
  BOTTOM_L10 w0.18: C34.2@66.631,7.959 67.087,7.959 67.252,8.123 v6(67.252,8.631) ; v2(69.383,29.717) 69.396,29.731 69.396,29.809 69.661,30.074 C196.2@69.916,30.074 ; v1(70.664,36.493) 71.084,36.074 C192.2@71.916,36.074 ; C197.2@72.041,29.774 v4(72.441,29.774) C190.2@72.841,29.774 ; C182.2@74.041,29.774 74.056,29.774 74.193,29.637 74.303,29.637 v1(74.316,29.624) ; C183.2@75.091,29.774 75.266,29.774 v1(75.416,29.624) ; C181.2@77.416,29.774 77.678,29.774 77.715,29.811 77.803,29.811 v1(77.816,29.824)
  BOTTOM_L10 w0.2: v3(74.316,36.074) C191.2@74.616,36.074 ; v3(75.416,36.074) C194.2@75.716,36.074
  BOTTOM_L10 w0.3: L20.1@42.454,29.686 42.454,29.701 42.604,29.851 42.619,29.851 43.07,30.302 43.07,31.05 43.369,31.349 v5(44.507,31.349) ; v3(65.9,21.2) 66.168,20.932 66.685,20.932 TP86.X@66.761,20.856 ; v6(69.481,10.137) 70.181,10.837 L2.2@70.181,11.134
  other v1: 72.531,19.834 66.759,21.549 67.541,22.331 69.441,22.331 82.211,27.309 80.116,29.249 69.383,29.717 72.441,29.774 80.09,31.049 46.311,32.099 80.116,32.249 69.07,32.85 69.066,34.049 38.402,34.542 44.879,35.581 69.091,35.849 74.316,36.074 75.416,36.074 77.236,37.747
  other v2: 66.759,22.069 67.021,22.331 68.921,22.331 76.991,27.924 74.316,29.624 75.416,29.624 72.441,29.774 77.816,29.824 45.761,31.849 38.402,34.542 80.37,34.548 44.879,35.581 79.594,35.874 74.316,36.074 75.416,36.074 42.079,36.144 70.664,36.493
  other v3: 74.316,29.624 75.416,29.624 69.383,29.717 72.441,29.774 77.816,29.824 44.507,31.349 42.079,36.144 70.664,36.493
  other v4: 65.9,21.2 74.316,29.624 75.416,29.624 69.383,29.717 77.816,29.824 44.507,31.349 38.402,34.542 44.879,35.581 74.316,36.074 75.416,36.074 42.079,36.144 70.664,36.493
  other v5: 76.991,27.924 74.316,29.624 75.416,29.624 69.383,29.717 72.441,29.774 77.816,29.824 80.116,32.249 38.402,34.542 44.879,35.581 74.316,36.074 75.416,36.074 42.079,36.144 70.664,36.493
+1V8: C134.2 C135.1 C169.2 C170.2 L11.1 L12.1 L13.1 L14.1 L15.1 L17.1 R21.2 R22.2 R218.1 R265.1 TP84.X U23.38 U23.47 U27_1.6 U27_1.11 | length 57.2
  TOP_L1 w0.2: v2(52.795,13.902) 53.168,13.529 R218.1@53.888,13.529
  TOP_L1 w0.5: R21.2@15.69,85.309 17.826,85.309 ; R22.2@15.698,83.341 18.126,83.341
  L5 w1: v2(52.795,13.902) 52.795,11.694 56.207,8.282 62.609,8.282 66.026,11.7 74.576,11.7 74.976,12.1 76.426,12.1 78.125,13.799 v6(78.125,21.899)
  L8 w0.3: v5@37.637,92.76 v4(37.642,92.766)
  BOTTOM_L10 w0.127: C169.2@39.298,86.016 39.662,86.016 v3(39.882,86.236) 39.882,86.818 40.08,87.016 U23.38@40.573,87.016 ; C170.2@39.298,91.616 39.623,91.616 v3(39.801,91.438) 39.801,91.303 39.936,91.303 39.936,90.697 40.016,90.616 U23.47@40.573,90.616 ; R265.1@73.321,19.127 73.624,19.127 74.011,19.514 76.28,19.514
  BOTTOM_L10 w0.2: L17.1@42.923,83.041 42.923,82.3 C134.2@42.926,82.3 ; U27_1.11@73.931,15.109 U27_1.6@75.531,15.109 U27_1.6@75.831,15.109
  BOTTOM_L10 w0.3: v4(37.642,92.766) C135.1@38.923,92.766 ; v5(42.348,82.663) 42.348,82.798 42.533,82.983 42.865,82.983 L17.1@42.923,83.041
  other v1: 52.795,13.902
  other v3: 42.348,82.663 37.642,92.766
  other v4: 42.348,82.663 39.882,86.236 39.801,91.438
  other v5: 52.795,13.902 39.882,86.236 39.801,91.438 37.642,92.766
  other v6: 83.626,48.8 84.426,48.8 85.226,48.8 83.626,49.6 84.426,49.6 85.226,49.6 63.1,76.001 63.9,76.001 63.1,76.801 63.9,76.801 63.1,77.601 63.9,77.601 63.1,78.401 63.9,78.401 16.926,84.05 17.726,84.05 18.526,84.05 19.326,84.05 16.926,84.85 17.726,84.85 18.526,84.85 19.326,84.85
